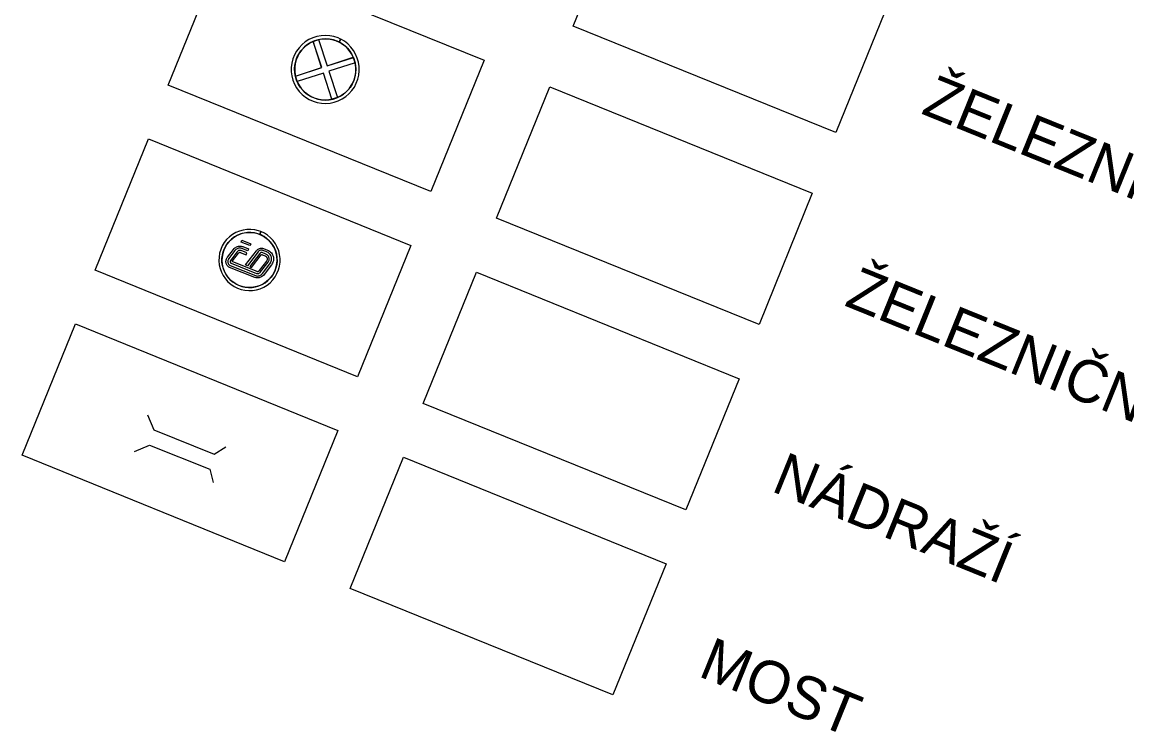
# Model space of a CAD drawing. Extents: x -522763 to -519637, y -1191176 to -1188936.
# Drawn here: x -522762.6 to -522372.7, y -1190060.2 to -1189809.7 of the extents above; entities that cross this region are included whole.
import ezdxf

# ---------------------------------------------------------------- set-up
doc = ezdxf.new("R2010")
doc.units = 0
for name, color, linetype in [('Implicitní', 7, 'Continuous'), ('most_s', 7, 'Continuous'), ('nadrazi_s', 7, 'Continuous'), ('zel_prejezd_s', 7, 'Continuous')]:
    doc.layers.add(name, color=color, linetype=linetype)

msp = doc.modelspace()

# ---------------------------------------------------------------- linework, layer by layer
at = {"layer": 'Implicitní'}
for points in [[(-522549.31, -1189764.79), (-522456.63, -1189802.35), (-522475.41, -1189848.69), (-522568.09, -1189811.13)], [(-522692.27, -1189785.63), (-522599.58, -1189823.18), (-522618.36, -1189869.52), (-522711.04, -1189831.98)], [(-522576.41, -1189832.56), (-522483.73, -1189870.11), (-522502.5, -1189916.45), (-522595.18, -1189878.91)], [(-522718.04, -1189850.94), (-522625.39, -1189888.56), (-522644.2, -1189934.89), (-522736.85, -1189897.26)], [(-522602.23, -1189897.96), (-522509.57, -1189935.59), (-522528.38, -1189981.91), (-522621.04, -1189944.29)], [(-522743.82, -1189916.24), (-522651.16, -1189953.86), (-522669.97, -1190000.19), (-522762.63, -1189962.57)], [(-522628, -1189963.27), (-522535.35, -1190000.89), (-522554.16, -1190047.21), (-522646.81, -1190009.59)]]:
    msp.add_lwpolyline(points, close=True, dxfattribs=at)
at = {"layer": 'most_s'}
for points in [[(-522718.34, -1189948.28), (-522716.08, -1189953.64), (-522694.83, -1189962.22), (-522690.68, -1189959.62)], [(-522722.96, -1189961.28), (-522717.62, -1189958.98), (-522696.33, -1189967.48), (-522695.14, -1189972.23)]]:
    msp.add_lwpolyline(points, dxfattribs=at)
at = {"layer": 'nadrazi_s'}
for points in [[(-522678.36, -1189883.63), (-522679.21, -1189883.34), (-522680.53, -1189883.02), (-522681.89, -1189882.87), (-522683.26, -1189882.9), (-522684.61, -1189883.1), (-522685.93, -1189883.47), (-522687.19, -1189884), (-522688.37, -1189884.68), (-522689.45, -1189885.51), (-522690.43, -1189886.47), (-522691.27, -1189887.55), (-522691.97, -1189888.72), (-522692.52, -1189889.97), (-522692.91, -1189891.28), (-522693.12, -1189892.63), (-522693.17, -1189894), (-522693.04, -1189895.36), (-522692.74, -1189896.69), (-522692.28, -1189897.97), (-522691.66, -1189899.19), (-522690.89, -1189900.32), (-522689.98, -1189901.34), (-522688.95, -1189902.24), (-522687.82, -1189903), (-522686.6, -1189903.62), (-522685.31, -1189904.07), (-522683.97, -1189904.36), (-522682.61, -1189904.47), (-522681.25, -1189904.42), (-522679.9, -1189904.19), (-522678.59, -1189903.8), (-522677.34, -1189903.24), (-522676.18, -1189902.53), (-522675.11, -1189901.68), (-522674.16, -1189900.7), (-522673.33, -1189899.6), (-522672.66, -1189898.42), (-522672.14, -1189897.15), (-522671.78, -1189895.84), (-522671.59, -1189894.48), (-522671.57, -1189893.12), (-522671.73, -1189891.76), (-522672.06, -1189890.43), (-522672.55, -1189889.16), (-522673.2, -1189887.95), (-522673.99, -1189886.84), (-522674.92, -1189885.84), (-522675.97, -1189884.96), (-522677.12, -1189884.23), (-522678.35, -1189883.64)], [(-522678.76, -1189884.64), (-522678.36, -1189883.63)], [(-522678.35, -1189883.64), (-522678.75, -1189884.64)], [(-522673.34, -1189897.28), (-522672.95, -1189896.11), (-522672.72, -1189894.91), (-522672.64, -1189893.68), (-522672.72, -1189892.45), (-522672.95, -1189891.24), (-522673.33, -1189890.08), (-522673.85, -1189888.96), (-522674.52, -1189887.93), (-522675.3, -1189886.98), (-522676.2, -1189886.14), (-522677.2, -1189885.43), (-522678.28, -1189884.84), (-522679.43, -1189884.4), (-522680.62, -1189884.1), (-522681.85, -1189883.96), (-522683.08, -1189883.97), (-522684.29, -1189884.14), (-522685.48, -1189884.45), (-522686.62, -1189884.92), (-522687.69, -1189885.53), (-522688.67, -1189886.27), (-522689.56, -1189887.12), (-522690.33, -1189888.08), (-522690.97, -1189889.13), (-522691.47, -1189890.25), (-522691.83, -1189891.43), (-522692.04, -1189892.64), (-522692.09, -1189893.87), (-522691.99, -1189895.09), (-522691.73, -1189896.3), (-522691.33, -1189897.46), (-522690.78, -1189898.56), (-522690.09, -1189899.58), (-522689.29, -1189900.51), (-522688.37, -1189901.33), (-522687.36, -1189902.02), (-522686.26, -1189902.58), (-522685.11, -1189903), (-522683.91, -1189903.28), (-522682.68, -1189903.39), (-522681.45, -1189903.35), (-522680.24, -1189903.16), (-522679.06, -1189902.82), (-522677.93, -1189902.33), (-522676.87, -1189901.7), (-522675.9, -1189900.94), (-522675.04, -1189900.07), (-522674.29, -1189899.09), (-522673.67, -1189898.03), (-522673.34, -1189897.28)], [(-522678.75, -1189884.64), (-522678.01, -1189884.97), (-522676.95, -1189885.59), (-522675.97, -1189886.34), (-522675.1, -1189887.2), (-522674.34, -1189888.17), (-522673.71, -1189889.23), (-522673.22, -1189890.36), (-522672.88, -1189891.54), (-522672.68, -1189892.75), (-522672.64, -1189893.98), (-522672.76, -1189895.21), (-522673.03, -1189896.41), (-522673.45, -1189897.56), (-522674.01, -1189898.65), (-522674.71, -1189899.67), (-522675.53, -1189900.59), (-522676.46, -1189901.39), (-522677.48, -1189902.08), (-522678.58, -1189902.63), (-522679.74, -1189903.04), (-522680.94, -1189903.29), (-522682.17, -1189903.4), (-522683.39, -1189903.34), (-522684.61, -1189903.14), (-522685.78, -1189902.78), (-522686.9, -1189902.27), (-522687.95, -1189901.63), (-522688.91, -1189900.86), (-522689.77, -1189899.98), (-522690.51, -1189899), (-522691.11, -1189897.93), (-522691.58, -1189896.79), (-522691.9, -1189895.6), (-522692.07, -1189894.38), (-522692.08, -1189893.15), (-522691.94, -1189891.93), (-522691.64, -1189890.74), (-522691.2, -1189889.59), (-522690.61, -1189888.51), (-522689.9, -1189887.51), (-522689.06, -1189886.61), (-522688.11, -1189885.82), (-522687.08, -1189885.16), (-522685.97, -1189884.63), (-522684.8, -1189884.25), (-522683.59, -1189884.02), (-522682.36, -1189883.94), (-522681.13, -1189884.02), (-522679.93, -1189884.25), (-522678.76, -1189884.64)], [(-522682.2, -1189888.6), (-522685.33, -1189887.35), (-522685.07, -1189886.71), (-522681.94, -1189887.97), (-522682.2, -1189888.6)], [(-522690.16, -1189892.71), (-522688.02, -1189889.93)], [(-522687.49, -1189890.35), (-522689.62, -1189893.12)], [(-522686.81, -1189890.86), (-522688.97, -1189893.67)], [(-522688.32, -1189893.93), (-522686.3, -1189891.31)], [(-522688.02, -1189889.93), (-522687.78, -1189889.65), (-522687.52, -1189889.41), (-522687.23, -1189889.2), (-522686.92, -1189889.03), (-522686.6, -1189888.89), (-522686.26, -1189888.8), (-522685.92, -1189888.76), (-522685.58, -1189888.75), (-522685.25, -1189888.79), (-522684.92, -1189888.87), (-522684.77, -1189888.93)], [(-522685.02, -1189889.56), (-522685.26, -1189889.48), (-522685.51, -1189889.44), (-522685.76, -1189889.43), (-522686.01, -1189889.45), (-522686.27, -1189889.5), (-522686.51, -1189889.59), (-522686.75, -1189889.7), (-522686.98, -1189889.85), (-522687.19, -1189890.02), (-522687.38, -1189890.22), (-522687.49, -1189890.35)], [(-522685.34, -1189890.35), (-522685.34, -1189890.35), (-522685.47, -1189890.3), (-522685.62, -1189890.28), (-522685.76, -1189890.27), (-522685.91, -1189890.29), (-522686.06, -1189890.32), (-522686.2, -1189890.37), (-522686.35, -1189890.44), (-522686.48, -1189890.53), (-522686.61, -1189890.64), (-522686.73, -1189890.76), (-522686.81, -1189890.86)], [(-522686.3, -1189891.31), (-522686.3, -1189891.31), (-522686.25, -1189891.24), (-522686.2, -1189891.18), (-522686.14, -1189891.12), (-522686.08, -1189891.08), (-522686.02, -1189891.04), (-522685.96, -1189891), (-522685.89, -1189890.98), (-522685.83, -1189890.96), (-522685.77, -1189890.95), (-522685.7, -1189890.95), (-522685.64, -1189890.96), (-522685.6, -1189890.98)], [(-522685.6, -1189890.98), (-522683.51, -1189891.81)], [(-522683.26, -1189891.18), (-522685.34, -1189890.35)], [(-522682.94, -1189890.39), (-522685.02, -1189889.56)], [(-522684.77, -1189888.93), (-522682.69, -1189889.76)], [(-522684.77, -1189888.93), (-522684.77, -1189888.93)], [(-522683.75, -1189895.42), (-522679.88, -1189890.39)], [(-522683.51, -1189891.81), (-522683.26, -1189891.18)], [(-522679.35, -1189890.82), (-522683.1, -1189895.68)], [(-522682.69, -1189889.76), (-522682.94, -1189890.39)], [(-522678.69, -1189891.35), (-522682.28, -1189896.01)], [(-522679.88, -1189890.39), (-522679.7, -1189890.18), (-522679.49, -1189890), (-522679.27, -1189889.83), (-522679.03, -1189889.7), (-522678.78, -1189889.6), (-522678.53, -1189889.53), (-522678.27, -1189889.49), (-522678.01, -1189889.49), (-522677.75, -1189889.52), (-522677.5, -1189889.59), (-522677.38, -1189889.63)], [(-522677.63, -1189890.26), (-522677.79, -1189890.21), (-522677.96, -1189890.17), (-522678.14, -1189890.17), (-522678.32, -1189890.18), (-522678.49, -1189890.22), (-522678.66, -1189890.28), (-522678.83, -1189890.36), (-522678.98, -1189890.46), (-522679.13, -1189890.58), (-522679.27, -1189890.72), (-522679.35, -1189890.82)], [(-522677.94, -1189891.05), (-522677.98, -1189891.03), (-522678.04, -1189891.02), (-522678.11, -1189891.01), (-522678.18, -1189891.02), (-522678.25, -1189891.03), (-522678.32, -1189891.05), (-522678.39, -1189891.08), (-522678.46, -1189891.12), (-522678.52, -1189891.17), (-522678.58, -1189891.22), (-522678.64, -1189891.29), (-522678.69, -1189891.35)], [(-522676.59, -1189891.59), (-522677.94, -1189891.05)], [(-522676.27, -1189890.8), (-522677.63, -1189890.26)], [(-522677.38, -1189889.63), (-522676.02, -1189890.17)], [(-522675.8, -1189894.46), (-522675.72, -1189894.35), (-522675.6, -1189894.14), (-522675.51, -1189893.92), (-522675.45, -1189893.7), (-522675.42, -1189893.46), (-522675.42, -1189893.23), (-522675.44, -1189892.99), (-522675.5, -1189892.76), (-522675.58, -1189892.54), (-522675.7, -1189892.33), (-522675.83, -1189892.14), (-522675.99, -1189891.97), (-522676.18, -1189891.82), (-522676.37, -1189891.69), (-522676.59, -1189891.59)], [(-522675.13, -1189894.98), (-522674.94, -1189894.69), (-522674.78, -1189894.39), (-522674.67, -1189894.06), (-522674.6, -1189893.73), (-522674.57, -1189893.39), (-522674.58, -1189893.04), (-522674.64, -1189892.71), (-522674.73, -1189892.38), (-522674.87, -1189892.06), (-522675.05, -1189891.77), (-522675.27, -1189891.5), (-522675.51, -1189891.26), (-522675.79, -1189891.05), (-522676.08, -1189890.89), (-522676.27, -1189890.8)], [(-522676.02, -1189890.17), (-522675.63, -1189890.36), (-522675.27, -1189890.59), (-522674.94, -1189890.86), (-522674.65, -1189891.18), (-522674.4, -1189891.53), (-522674.2, -1189891.9), (-522674.04, -1189892.3), (-522673.94, -1189892.72), (-522673.89, -1189893.15), (-522673.9, -1189893.58), (-522673.95, -1189894), (-522674.07, -1189894.42), (-522674.23, -1189894.81), (-522674.44, -1189895.18), (-522674.59, -1189895.39)], [(-522689.39, -1189896.26), (-522689.62, -1189896.15), (-522689.84, -1189896.01), (-522690.04, -1189895.84), (-522690.21, -1189895.64), (-522690.36, -1189895.42), (-522690.49, -1189895.19), (-522690.58, -1189894.93), (-522690.65, -1189894.67), (-522690.68, -1189894.4), (-522690.68, -1189894.12), (-522690.65, -1189893.84), (-522690.59, -1189893.57), (-522690.5, -1189893.3), (-522690.38, -1189893.05), (-522690.23, -1189892.81), (-522690.16, -1189892.71)], [(-522689.63, -1189893.13), (-522689.74, -1189893.3), (-522689.83, -1189893.47), (-522689.91, -1189893.65), (-522689.96, -1189893.84), (-522689.99, -1189894.03), (-522690.01, -1189894.22), (-522690, -1189894.41), (-522689.97, -1189894.6), (-522689.92, -1189894.78), (-522689.85, -1189894.95), (-522689.76, -1189895.11), (-522689.66, -1189895.25), (-522689.54, -1189895.38), (-522689.4, -1189895.49), (-522689.25, -1189895.58), (-522689.14, -1189895.63)], [(-522688.97, -1189893.67), (-522689.02, -1189893.74), (-522689.06, -1189893.82), (-522689.1, -1189893.9), (-522689.12, -1189893.98), (-522689.14, -1189894.07), (-522689.16, -1189894.15), (-522689.16, -1189894.24), (-522689.16, -1189894.32), (-522689.15, -1189894.4), (-522689.13, -1189894.48), (-522689.1, -1189894.55), (-522689.07, -1189894.61), (-522689.03, -1189894.68), (-522688.99, -1189894.73), (-522688.94, -1189894.78), (-522688.88, -1189894.81), (-522688.82, -1189894.84)], [(-522689.14, -1189895.63), (-522680.24, -1189899.19)], [(-522688.82, -1189894.84), (-522679.92, -1189898.4)], [(-522688.2, -1189894.36), (-522688.22, -1189894.35), (-522688.25, -1189894.33), (-522688.28, -1189894.31), (-522688.3, -1189894.29), (-522688.32, -1189894.26), (-522688.34, -1189894.23), (-522688.36, -1189894.2), (-522688.37, -1189894.16), (-522688.37, -1189894.13), (-522688.38, -1189894.09), (-522688.37, -1189894.06), (-522688.37, -1189894.02), (-522688.35, -1189893.99), (-522688.34, -1189893.96), (-522688.32, -1189893.93)], [(-522679.67, -1189897.77), (-522688.2, -1189894.36)], [(-522683.1, -1189895.68), (-522683.75, -1189895.42)], [(-522681.62, -1189896.27), (-522678.24, -1189891.88)], [(-522676.34, -1189894.05), (-522678.92, -1189897.39)], [(-522678.43, -1189897.87), (-522675.8, -1189894.46)], [(-522678.24, -1189891.88), (-522678.24, -1189891.87), (-522678.21, -1189891.85), (-522678.18, -1189891.83), (-522678.15, -1189891.81), (-522678.12, -1189891.79), (-522678.09, -1189891.78), (-522678.05, -1189891.77), (-522678.02, -1189891.77), (-522677.98, -1189891.77), (-522677.95, -1189891.78), (-522677.91, -1189891.79)], [(-522677.91, -1189891.79), (-522676.84, -1189892.22)], [(-522677.77, -1189898.41), (-522675.13, -1189894.98)], [(-522674.59, -1189895.4), (-522677.24, -1189898.83)], [(-522676.84, -1189892.22), (-522676.76, -1189892.26), (-522676.63, -1189892.33), (-522676.51, -1189892.42), (-522676.4, -1189892.53), (-522676.31, -1189892.64), (-522676.23, -1189892.77), (-522676.17, -1189892.91), (-522676.12, -1189893.05), (-522676.1, -1189893.2), (-522676.09, -1189893.35), (-522676.11, -1189893.5), (-522676.14, -1189893.65), (-522676.19, -1189893.79), (-522676.26, -1189893.92), (-522676.34, -1189894.05)], [(-522680.49, -1189899.82), (-522689.39, -1189896.26)], [(-522682.28, -1189896.01), (-522681.62, -1189896.27)], [(-522677.24, -1189898.83), (-522677.47, -1189899.1), (-522677.74, -1189899.34), (-522678.03, -1189899.55), (-522678.33, -1189899.72), (-522678.66, -1189899.86), (-522678.99, -1189899.95), (-522679.33, -1189900), (-522679.67, -1189900), (-522680.01, -1189899.96), (-522680.33, -1189899.88), (-522680.49, -1189899.82)], [(-522680.24, -1189899.19), (-522680, -1189899.27), (-522679.75, -1189899.31), (-522679.5, -1189899.32), (-522679.24, -1189899.3), (-522678.99, -1189899.25), (-522678.74, -1189899.17), (-522678.5, -1189899.05), (-522678.28, -1189898.9), (-522678.07, -1189898.73), (-522677.88, -1189898.53), (-522677.76, -1189898.4)], [(-522679.92, -1189898.4), (-522679.92, -1189898.4), (-522679.78, -1189898.45), (-522679.64, -1189898.47), (-522679.49, -1189898.48), (-522679.35, -1189898.46), (-522679.2, -1189898.43), (-522679.05, -1189898.38), (-522678.91, -1189898.31), (-522678.78, -1189898.22), (-522678.65, -1189898.12), (-522678.53, -1189898), (-522678.43, -1189897.87)], [(-522678.92, -1189897.39), (-522679, -1189897.51), (-522679.06, -1189897.57), (-522679.11, -1189897.63), (-522679.17, -1189897.68), (-522679.24, -1189897.72), (-522679.3, -1189897.75), (-522679.36, -1189897.78), (-522679.43, -1189897.79), (-522679.49, -1189897.8), (-522679.55, -1189897.8), (-522679.61, -1189897.79), (-522679.67, -1189897.77)]]:
    msp.add_lwpolyline(points, dxfattribs=at)
at = {"layer": 'zel_prejezd_s'}
for points in [[(-522650.19, -1189815.71), (-522651.1, -1189815.29), (-522652.54, -1189814.81), (-522654.03, -1189814.51), (-522655.54, -1189814.4), (-522657.06, -1189814.49), (-522658.55, -1189814.76), (-522660, -1189815.22), (-522661.37, -1189815.86), (-522662.66, -1189816.67), (-522663.83, -1189817.64), (-522664.87, -1189818.74), (-522665.76, -1189819.97), (-522666.49, -1189821.3), (-522667.05, -1189822.71), (-522667.43, -1189824.18), (-522667.62, -1189825.69), (-522667.61, -1189827.21), (-522667.41, -1189828.71), (-522667.03, -1189830.18), (-522666.46, -1189831.59), (-522665.72, -1189832.92), (-522664.82, -1189834.14), (-522663.77, -1189835.23), (-522662.59, -1189836.19), (-522661.3, -1189836.99), (-522659.92, -1189837.62), (-522658.47, -1189838.08), (-522656.98, -1189838.34), (-522655.46, -1189838.42), (-522653.95, -1189838.3), (-522652.46, -1189837.99), (-522651.03, -1189837.5), (-522649.66, -1189836.83), (-522648.4, -1189836), (-522647.25, -1189835.01), (-522646.23, -1189833.88), (-522645.36, -1189832.63), (-522644.66, -1189831.29), (-522644.13, -1189829.87), (-522643.78, -1189828.39), (-522643.63, -1189826.88), (-522643.67, -1189825.36), (-522643.9, -1189823.86), (-522644.31, -1189822.4), (-522644.91, -1189821), (-522645.68, -1189819.69), (-522646.6, -1189818.49), (-522647.67, -1189817.41), (-522648.87, -1189816.48), (-522650.18, -1189815.71)], [(-522650.72, -1189816.78), (-522649.94, -1189817.22), (-522648.83, -1189818.01), (-522647.82, -1189818.94), (-522646.94, -1189819.98), (-522646.2, -1189821.13), (-522645.61, -1189822.36), (-522645.18, -1189823.66), (-522644.91, -1189825), (-522644.82, -1189826.36), (-522644.9, -1189827.73), (-522645.15, -1189829.07), (-522645.57, -1189830.37), (-522646.15, -1189831.61), (-522646.88, -1189832.76), (-522647.75, -1189833.81), (-522648.75, -1189834.75), (-522649.86, -1189835.55), (-522651.06, -1189836.2), (-522652.33, -1189836.7), (-522653.66, -1189837.04), (-522655.01, -1189837.2), (-522656.38, -1189837.19), (-522657.73, -1189837.01), (-522659.05, -1189836.66), (-522660.32, -1189836.15), (-522661.51, -1189835.48), (-522662.61, -1189834.66), (-522663.59, -1189833.72), (-522664.45, -1189832.65), (-522665.17, -1189831.49), (-522665.73, -1189830.24), (-522666.14, -1189828.94), (-522666.37, -1189827.59), (-522666.44, -1189826.23), (-522666.33, -1189824.87), (-522666.05, -1189823.53), (-522665.6, -1189822.24), (-522664.99, -1189821.01), (-522664.24, -1189819.87), (-522663.34, -1189818.84), (-522662.33, -1189817.93), (-522661.2, -1189817.15), (-522659.99, -1189816.52), (-522658.71, -1189816.05), (-522657.38, -1189815.74), (-522656.02, -1189815.61), (-522654.65, -1189815.65), (-522653.3, -1189815.86), (-522651.99, -1189816.23), (-522650.73, -1189816.77)], [(-522646, -1189831.31), (-522645.45, -1189830.06), (-522645.08, -1189828.74), (-522644.87, -1189827.39), (-522644.83, -1189826.03), (-522644.96, -1189824.67), (-522645.27, -1189823.34), (-522645.74, -1189822.05), (-522646.37, -1189820.84), (-522647.14, -1189819.72), (-522648.06, -1189818.7), (-522649.09, -1189817.8), (-522650.23, -1189817.05), (-522651.45, -1189816.44), (-522652.74, -1189815.99), (-522654.08, -1189815.71), (-522655.44, -1189815.6), (-522656.81, -1189815.67), (-522658.15, -1189815.9), (-522659.46, -1189816.3), (-522660.7, -1189816.87), (-522661.87, -1189817.58), (-522662.93, -1189818.44), (-522663.88, -1189819.43), (-522664.69, -1189820.52), (-522665.36, -1189821.71), (-522665.88, -1189822.98), (-522666.23, -1189824.3), (-522666.41, -1189825.65), (-522666.42, -1189827.02), (-522666.26, -1189828.38), (-522665.92, -1189829.7), (-522665.43, -1189830.98), (-522664.77, -1189832.18), (-522663.97, -1189833.28), (-522663.04, -1189834.28), (-522661.98, -1189835.15), (-522660.83, -1189835.88), (-522659.59, -1189836.46), (-522658.29, -1189836.88), (-522656.95, -1189837.14), (-522655.59, -1189837.22), (-522654.22, -1189837.13), (-522652.88, -1189836.86), (-522651.58, -1189836.43), (-522650.35, -1189835.84), (-522649.2, -1189835.1), (-522648.16, -1189834.22), (-522647.23, -1189833.22), (-522646.44, -1189832.1), (-522646, -1189831.31)], [(-522656.9, -1189825.76), (-522659.92, -1189816.48), (-522658.02, -1189815.86)], [(-522656.89, -1189825.77), (-522659.91, -1189816.49), (-522658.01, -1189815.87)], [(-522658.02, -1189815.86), (-522655, -1189825.14)], [(-522658.01, -1189815.87), (-522654.99, -1189825.15)], [(-522650.73, -1189816.77), (-522650.19, -1189815.71)], [(-522650.18, -1189815.71), (-522650.72, -1189816.78)], [(-522655, -1189825.14), (-522645.72, -1189822.12), (-522645.1, -1189824.03)], [(-522654.99, -1189825.15), (-522645.71, -1189822.13), (-522645.09, -1189824.03)], [(-522645.1, -1189824.03), (-522654.38, -1189827.05)], [(-522645.09, -1189824.03), (-522654.37, -1189827.05)], [(-522666.18, -1189828.79), (-522656.9, -1189825.76)], [(-522656.28, -1189827.67), (-522665.56, -1189830.69), (-522666.18, -1189828.79)], [(-522666.17, -1189828.79), (-522656.89, -1189825.77)], [(-522656.27, -1189827.67), (-522665.55, -1189830.69), (-522666.17, -1189828.79)], [(-522653.26, -1189836.95), (-522656.28, -1189827.67)], [(-522653.25, -1189836.95), (-522656.27, -1189827.67)], [(-522654.38, -1189827.05), (-522651.35, -1189836.33), (-522653.26, -1189836.95)], [(-522654.37, -1189827.05), (-522651.35, -1189836.33), (-522653.25, -1189836.95)]]:
    msp.add_lwpolyline(points, dxfattribs=at)

# ---------------------------------------------------------------- texts
at = {"layer": 'Implicitní'}
for s, rotation, p in [('ROZHLEDOVÉ POLE KŘIŽOVATKY', 337.9379, (-522420.88, -1189778.1)), ('ŽELEZNIČNÍ TRAŤ CELOSTÁTNÍ', 337.9379, (-522445.67, -1189841.86)), ('ŽELEZNIČNÍ PŘEJEZD', 337.9487, (-522472.76, -1189909.62)), ('NÁDRAŽÍ', 337.9005, (-522498.64, -1189975.1)), ('MOST', 337.9005, (-522524.41, -1190040.41))]:
    msp.add_text(s, height=15, rotation=rotation, dxfattribs=at).set_placement(p)

doc.saveas('drawing.dxf')
